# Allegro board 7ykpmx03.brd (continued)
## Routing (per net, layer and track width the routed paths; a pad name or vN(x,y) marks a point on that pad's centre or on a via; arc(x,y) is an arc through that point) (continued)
PE_CPU_OCP_15_DP: length 66.5
  TOP w0.127: 178.31,77.5 178.18,77.37 174.7,77.37 174.59,77.48 174.36,77.48 174.24,77.37 174.02,77.37 173.89,77.49 173.68,77.49 173.56,77.37 173.27,77.37 172.47,78.17 172.47,78.36 172.57,78.46 172.57,78.64 172.47,78.74 172.47,78.97 172.59,79.1 172.59,79.3 172.47,79.43 172.47,79.63 172.59,79.76 172.59,79.93 172.47,80.06 172.47,80.45 172.59,81.18 172.25,83.13 172.69,85.63 172.47,86.91 172.47,87.38 171.7,88.14 171.45,88.14 171.27,88.17 169.83,87.92 167.33,88.36 164.83,87.92 162.33,88.36 159.83,87.92 157.33,88.36 154.82,87.92 152.32,88.36 149.82,87.92 148.57,88.14 147.96,88.14 143.94,84.12 143.73,84.12 143.49,84.08 142.01,84.35 139.51,83.9 137.01,84.35 134.94,83.98 134.12,84.12 132.59,84.12 131.83,84.88 131.83,85.51 131.98,85.65 P_OCP.B66
  TOP w0.152: P_CPU_OCP_15_P.1 178.31,77.5
PE_OCP_CPU_0_DN: length 66.7
  TOP w0.127: P_OCP.A17 94.86,91.84 95.01,91.98 95.01,93.79 94.01,94.79 91.67,94.79 89.31,97.16 87.81,97.16 86.97,96.32 86.04,96.32 85.46,96.9 85.46,97.79 85.33,97.92 84.56,97.92 84.44,97.79 84.44,96.79 83.96,96.32 83.29,96.32 82.81,96.79 82.81,97.69 82.51,97.99 82.09,97.99 81.79,97.69 81.79,96.79 81.31,96.32 80.64,96.32 80.16,96.79 80.16,97.69 79.86,97.99 79.44,97.99 79.14,97.69 79.14,96.79 78.67,96.32 77.99,96.32 77.52,96.79 77.52,97.69 77.22,97.99 76.8,97.99 76.5,97.69 76.5,96.79 76.17,96.47 75.19,96.47 74.87,96.79 74.87,97.69 74.7,97.87 73.74,97.87 73.02,97.16 72.72,97.16 72.54,96.98 72.36,96.98 72.19,97.16 71.93,97.16 71.76,96.98 71.58,96.98 71.4,97.16 70.74,97.16 70.54,97.36 70.36,97.36 70.23,97.49 70.23,97.66 70.1,97.79 69.9,97.79 69.75,97.94 69.75,98.15 64.8,103.1 63.69,103.1 62.51,103.3 60.04,102.87 57.54,103.31 55.04,102.87 53.76,103.1 52.7,103.1 52.58,102.97
  TOP w0.152: P_OCP_CPU_0_N1.1 52.58,102.97
PE_OCP_CPU_0_DP: length 66.7
  TOP w0.127: P_OCP.A18 95.46,91.84 95.31,91.98 95.31,93.92 94.13,95.1 91.79,95.1 89.43,97.46 87.68,97.46 86.84,96.62 86.17,96.62 85.76,97.03 85.76,97.92 85.46,98.22 84.44,98.22 84.13,97.92 84.13,96.92 83.83,96.62 83.41,96.62 83.11,96.92 83.11,97.82 82.64,98.3 81.96,98.3 81.49,97.82 81.49,96.92 81.19,96.62 80.77,96.62 80.47,96.92 80.47,97.82 79.99,98.3 79.32,98.3 78.84,97.82 78.84,96.92 78.54,96.62 78.12,96.62 77.82,96.92 77.82,97.82 77.34,98.3 76.67,98.3 76.19,97.82 76.19,96.92 76.05,96.77 75.32,96.77 75.17,96.92 75.17,97.82 74.82,98.17 73.61,98.17 72.9,97.46 70.87,97.46 64.92,103.4 63.72,103.4 62.5,103.61 60.04,103.18 57.54,103.62 55.04,103.18 53.79,103.4 52.7,103.4 52.58,103.53
  TOP w0.152: P_OCP_CPU_0_P1.1 52.58,103.53
PE_OCP_CPU_1_DN: length 66.7
  TOP w0.127: 69.44,108.97 69.57,108.84 69.57,108.02 69.47,107.46 69.79,105.68 69.57,104.45 69.57,103.61 71.83,101.35 73.3,101.35 73.78,101.82 73.78,102.9 74.07,103.2 74.5,103.2 74.79,102.9 74.79,99.97 75.27,99.49 75.95,99.49 76.42,99.97 76.42,102.9 76.72,103.2 77.14,103.2 77.44,102.9 77.44,99.97 77.82,99.59 78.69,99.59 79.07,99.97 79.07,102.95 79.38,103.26 79.8,103.26 80.09,102.98 80.09,99.97 80.56,99.49 81.24,99.49 81.72,99.97 81.72,102.62 81.84,102.74 82.61,102.74 82.73,102.62 82.73,102.53 83.92,101.35 84.56,101.35 85.83,101.12 87.7,101.45 87.92,101.41 93.14,96.19 95.02,96.19 96.81,94.4 96.81,91.98 96.66,91.84 P_OCP.A20
  TOP w0.152: P_OCP_CPU_1_N1.1 69.44,108.97
PE_OCP_CPU_1_DP: length 66.7
  TOP w0.127: P_OCP.A21 97.26,91.84 97.11,91.98 97.11,94.53 95.15,96.49 93.27,96.49 88.07,101.69 87.7,101.76 85.83,101.43 84.58,101.65 84.05,101.65 83.04,102.66 83.04,102.74 82.73,103.05 81.72,103.05 81.41,102.74 81.41,100.09 81.11,99.8 80.69,99.8 80.39,100.09 80.39,103.1 79.93,103.57 79.25,103.57 78.76,103.08 78.76,100.09 78.57,99.9 77.94,99.9 77.75,100.09 77.75,103.03 77.27,103.5 76.59,103.5 76.12,103.03 76.12,100.09 75.82,99.8 75.4,99.8 75.1,100.09 75.1,103.03 74.62,103.5 73.95,103.5 73.47,103.03 73.47,101.95 73.17,101.65 71.96,101.65 69.88,103.73 69.88,104.42 70.1,105.68 69.78,107.46 69.88,108 69.88,108.84 70,108.97
  TOP w0.152: P_OCP_CPU_1_P1.1 70,108.97
PE_OCP_CPU_2_DN: length 66.6
  TOP w0.127: P_OCP.A23 98.46,91.84 98.61,91.98 98.61,94.76 94.88,98.49 93.51,98.49 86.86,105.14 86.41,105.14 85.44,104.17 85.01,104.17 84.29,104.89 84.29,105.32 85.15,106.18 85.15,106.36 84.61,106.9 84.43,106.9 84.01,106.49 83.58,106.49 82.86,107.21 82.86,107.64 83.54,108.31 83.54,108.49 82.99,109.03 82.81,109.03 82.37,108.59 81.94,108.59 81.22,109.31 81.22,109.74 81.52,110.03 81.52,110.51 77.65,114.38 76.15,114.38 76.02,114.25 75.82,114.25 75.69,114.38 75.49,114.38 75.36,114.25 75.13,114.25 75.01,114.38 74.78,114.38 74.68,114.27 74.47,114.27 74.37,114.38 74.17,114.38 74.04,114.25 73.84,114.25 73.71,114.38 73.33,114.38 69.55,118.16 69.55,118.95 69.66,119.59 69.32,121.51 69.55,122.79 69.55,122.94 67.08,125.4 66.94,125.4 66.82,125.53 66.82,125.67 66.52,125.96 64.14,125.96 64.01,125.83
  TOP w0.152: P_OCP_CPU_2_N1.1 64.01,125.83
PE_OCP_CPU_2_DP: length 66.6
  TOP w0.127: P_OCP.A24 99.06,91.84 98.91,91.98 98.91,94.89 95.01,98.79 93.64,98.79 86.99,105.45 86.29,105.45 85.32,104.48 85.14,104.48 84.6,105.02 84.6,105.2 85.46,106.06 85.46,106.49 84.74,107.21 84.31,107.21 83.89,106.79 83.71,106.79 83.17,107.33 83.17,107.51 83.84,108.18 83.84,108.62 83.12,109.33 82.69,109.33 82.25,108.89 82.07,108.89 81.53,109.43 81.53,109.61 81.82,109.91 81.82,110.63 77.77,114.68 73.46,114.68 69.85,118.29 69.85,118.92 69.97,119.59 69.63,121.51 69.85,122.76 69.85,123.06 66.65,126.26 64.14,126.26 64.01,126.39
  TOP w0.152: P_OCP_CPU_2_P1.1 64.01,126.39
PE_OCP_CPU_3_DN: length 66.5
  TOP w0.127: P_OCP.A26 100.26,91.84 100.41,91.98 100.41,92.71 100.62,93.92 100.41,95.12 100.41,95.48 94.97,100.91 93.65,100.91 86.95,107.62 86.95,108.29 88.43,109.77 88.43,109.95 87.89,110.49 87.71,110.49 86.02,108.8 85.59,108.8 84.87,109.52 84.87,109.95 87.82,112.9 87.82,113.32 87.52,113.62 87.1,113.62 84.15,110.67 83.71,110.67 83,111.39 83,111.82 86.07,114.9 86.07,115.32 85.77,115.62 85.35,115.62 82.48,112.75 81.81,112.75 81,113.56 81,114.41 81.22,115.64 80.8,118.04 81,119.21 81,120.27 80.87,120.4
  TOP w0.152: P_OCP_CPU_3_N1.1 80.87,120.4
PE_OCP_CPU_3_DP: length 66.5
  TOP w0.127: 81.43,120.4 81.31,120.27 81.31,119.19 81.11,118.04 81.53,115.64 81.31,114.39 81.31,113.69 81.94,113.06 82.36,113.06 85.22,115.92 85.9,115.92 86.38,115.45 86.38,114.77 83.3,111.7 83.3,111.52 83.84,110.98 84.02,110.98 86.97,113.93 87.64,113.93 88.12,113.45 88.12,112.78 85.17,109.83 85.17,109.65 85.71,109.11 85.89,109.11 87.58,110.79 88.01,110.79 88.73,110.07 88.73,109.64 87.25,108.16 87.25,107.74 93.78,101.22 95.1,101.22 100.71,95.6 100.71,95.15 100.93,93.92 100.71,92.69 100.71,91.98 100.86,91.84 P_OCP.A27
  TOP w0.152: P_OCP_CPU_3_P1.1 81.43,120.4
PE_OCP_CPU_4_DN: length 66.5
  TOP w0.127: 80.87,131.83 81,131.7 81,128.75 82.88,126.87 87.39,126.87 88.42,125.84 88.42,125.6 88.73,125.3 89.75,125.3 90.05,125.6 90.05,127.1 90.18,127.23 91.21,127.23 91.39,127.05 91.39,126.62 91.44,126.32 91.17,124.77 91.61,122.27 91.17,119.76 91.61,117.26 91.17,114.76 91.61,112.26 91.17,109.76 91.61,107.26 91.39,106.01 91.39,105.46 94.16,102.69 97.05,102.69 106.22,93.52 106.22,91.98 106.07,91.84 P_OCP.A30
  TOP w0.152: P_OCP_CPU_4_N.1 80.87,131.83
PE_OCP_CPU_4_DP: length 66.5
  TOP w0.127: P_OCP.A31 106.67,91.84 106.52,91.98 106.52,93.65 97.18,103 94.28,103 91.69,105.59 91.69,105.98 91.92,107.26 91.48,109.76 91.92,112.26 91.48,114.76 91.92,117.26 91.48,119.76 91.92,122.27 91.48,124.77 91.75,126.32 91.69,126.65 91.69,127.18 91.34,127.53 90.05,127.53 89.75,127.23 89.75,125.73 89.62,125.6 88.85,125.6 88.73,125.73 88.73,125.97 87.51,127.18 83.01,127.18 81.31,128.88 81.31,131.7 81.43,131.83
  TOP w0.152: P_OCP_CPU_4_P4.1 81.43,131.83
PE_OCP_CPU_5_DN: length 66.5
  TOP w0.127: P_OCP.A33 107.87,91.84 108.02,91.98 108.02,94.16 98.02,104.17 94.62,104.17 93.55,105.23 93.55,106.02 93.77,107.27 93.33,109.77 93.77,112.28 93.33,114.78 93.77,117.28 93.33,119.78 93.77,122.28 93.33,124.78 93.58,126.2 93.55,126.36 93.55,126.95 94.36,127.76 95.34,127.76 95.64,127.46 95.64,126.37 95.81,126.2 96.79,126.2 96.92,126.33 96.92,126.87 97.22,127.18 98.81,127.18 99.44,126.54 100.08,126.54 100.71,127.18 101.98,127.18 103.86,129.06 103.86,131.7 103.73,131.83
  TOP w0.152: P_OCP_CPU_5_N.1 103.73,131.83
PE_OCP_CPU_5_DP: length 66.5
  TOP w0.127: 104.29,131.83 104.17,131.7 104.17,128.93 102.11,126.87 100.84,126.87 100.2,126.24 99.31,126.24 98.68,126.87 97.35,126.87 97.22,126.75 97.22,126.2 96.92,125.9 95.69,125.9 95.34,126.25 95.34,127.33 95.21,127.46 94.49,127.46 93.85,126.82 93.85,126.39 93.89,126.2 93.64,124.78 94.08,122.28 93.64,119.78 94.08,117.28 93.64,114.78 94.08,112.28 93.64,109.77 94.08,107.27 93.85,106 93.85,105.36 94.74,104.47 98.14,104.47 108.32,94.29 108.32,91.98 108.47,91.84 P_OCP.A34
  TOP w0.152: P_OCP_CPU_5_P.1 104.29,131.83
PE_OCP_CPU_6_DN: length 66.6
  TOP w0.127: P_OCP.A36 109.67,91.84 109.82,91.98 109.82,95.25 110.13,95.55 110.54,95.55 111.02,96.04 111.02,96.47 110.89,96.6 110.06,96.6 108.3,96.9 107.9,96.9 107.59,97.21 107.59,98.17 108.02,98.6 108.27,98.6 108.37,98.62 110.45,98.25 112.43,98.6 112.81,98.6 112.94,98.73 112.94,99.57 112.81,99.69 112.44,99.69 110.88,99.42 109.16,99.72 108.99,99.69 108.4,99.69 107.97,100.13 107.97,101.09 108.27,101.4 109.35,101.4 110.48,101.2 111.61,101.4 111.89,101.4 112.05,101.56 112.05,102.11 112.23,103.16 112.05,104.22 112.05,104.47 111.92,104.6 110.36,104.6 110.13,104.37 110.13,102.79 109.83,102.49 108.59,102.49 108.28,102.79 108.28,104.47 108.15,104.6 107.01,104.6 106.73,104.32 106.73,103.9 106.51,102.65 106.73,101.39 106.73,100.37 106.43,100.06 105.03,100.06 104.55,100.54 104.55,102.84 104.38,103.01 104.13,103.01 103.11,102.83 102.08,103.01 101.64,103.01 101.34,103.32 101.34,104.37 101.64,104.67 101.98,104.67 103.03,104.49 104.09,104.67 104.43,104.67 104.55,104.8 104.55,105.89 103.86,106.58 103.86,108.84 103.73,108.97
  TOP w0.152: P_OCP_CPU_6_N.1 103.73,108.97
PE_OCP_CPU_6_DP: length 66.6
  TOP w0.127: 104.29,108.97 104.17,108.84 104.17,106.7 104.86,106.01 104.86,104.67 104.55,104.37 104.11,104.37 103.03,104.18 101.95,104.37 101.77,104.37 101.64,104.24 101.64,103.44 101.77,103.32 102.11,103.32 103.11,103.14 104.1,103.32 104.5,103.32 104.86,102.97 104.86,100.67 105.16,100.37 106.3,100.37 106.43,100.49 106.43,101.37 106.2,102.65 106.43,103.92 106.43,104.44 106.88,104.9 108.28,104.9 108.58,104.6 108.58,102.92 108.71,102.79 109.7,102.79 109.83,102.92 109.83,104.49 110.24,104.9 112.05,104.9 112.36,104.6 112.36,104.24 112.54,103.16 112.36,102.08 112.36,101.43 112.01,101.09 111.63,101.09 110.48,100.89 109.32,101.09 108.4,101.09 108.27,100.97 108.27,100.25 108.53,100 108.97,100 109.16,100.03 110.88,99.73 112.41,100 112.94,100 113.24,99.69 113.24,98.6 112.94,98.3 112.45,98.3 110.45,97.94 108.37,98.31 108.3,98.3 108.15,98.3 107.89,98.04 107.89,97.34 108.03,97.21 108.33,97.21 110.09,96.9 111.02,96.9 111.32,96.6 111.32,95.91 110.66,95.25 110.25,95.25 110.12,95.12 110.12,91.98 110.27,91.84 P_OCP.A37
  TOP w0.152: P_OCP_CPU_6_P.1 104.29,108.97
PE_OCP_CPU_7_DN: length 66.6
  TOP w0.127: 103.73,120.4 103.86,120.27 103.86,118.75 104.04,117.72 103.64,115.41 103.86,114.14 103.86,113.59 104.29,113.16 105.11,113.16 105.54,113.59 105.54,115.9 105.79,116.15 106.56,116.15 106.69,116.03 106.69,112.88 106.99,112.57 108.26,112.57 108.57,112.88 108.57,115.93 108.79,116.15 109.47,116.15 109.73,115.9 109.73,113.23 110.24,112.73 111.38,112.73 111.68,113.03 111.68,115.87 111.89,116.08 113.78,116.08 114.04,115.82 114.04,114.86 113.91,114.73 113.08,114.73 112.78,114.43 112.78,113.2 113.12,112.85 114.12,112.85 114.5,112.47 114.5,110.54 114.2,108.82 114.65,106.24 114.1,103.08 114.63,100.02 114.63,97.92 111.62,94.91 111.62,91.98 111.47,91.84 P_OCP.A39
  TOP w0.152: P_OCP_CPU_7_N.1 103.73,120.4
PE_OCP_CPU_7_DP: length 66.6
  TOP w0.127: P_OCP.A40 112.07,91.84 111.92,91.98 111.92,94.78 114.94,97.79 114.94,100.05 114.41,103.08 114.96,106.24 114.51,108.82 114.81,110.52 114.81,112.6 114.25,113.16 113.25,113.16 113.08,113.32 113.08,114.3 113.21,114.43 114.04,114.43 114.34,114.73 114.34,115.95 113.91,116.38 111.76,116.38 111.38,116 111.38,113.16 111.25,113.03 110.36,113.03 110.03,113.36 110.03,116.03 109.6,116.46 108.66,116.46 108.26,116.06 108.26,113 108.14,112.88 107.12,112.88 106.99,113 106.99,116.15 106.68,116.46 105.67,116.46 105.23,116.03 105.23,113.72 104.98,113.46 104.42,113.46 104.17,113.72 104.17,114.16 103.94,115.41 104.35,117.72 104.17,118.77 104.17,120.27 104.29,120.4
  TOP w0.152: P_OCP_CPU_7_P.1 104.29,120.4
PE_OCP_CPU_8_DN: length 66.5
  TOP w0.127: P_OCP.A44 118.78,91.84 118.93,91.98 118.93,92.33 118.49,92.77 118.49,93.19 118.32,94.16 118.49,95.13 118.49,95.91 116.1,98.3 116.1,100.37 116.15,100.62 115.72,103.08 116.29,106.35 115.85,108.86 116.14,110.49 116.03,111.12 116.03,112.6 116.64,113.21 117.71,113.21 117.95,113.45 117.95,114.21 117.73,114.43 116.54,114.43 116.22,114.75 116.22,116.08 116.53,116.38 119.25,116.38 119.68,115.95 119.68,113.54 119.81,113.41 121.03,113.41 121.16,113.54 121.16,116 121.49,116.33 122.55,116.33 122.86,116.03 122.86,114.02 123.22,113.66 123.83,113.66 123.95,113.79 123.95,116 124.26,116.31 125.35,116.31 125.65,116 125.65,112.78 125.78,112.65 126.59,112.65 126.72,112.78 126.72,113.29 127.02,114.96 126.57,117.46 126.78,118.64 126.72,119 126.72,120.27 126.59,120.4
  TOP w0.152: P_OCP_CPU_8_N.1 126.59,120.4
PE_OCP_CPU_8_DP: length 66.5
  TOP w0.127: P_OCP.A45 119.38,91.84 119.23,91.98 119.23,92.46 118.8,92.89 118.8,93.22 118.63,94.16 118.8,95.11 118.8,96.04 116.41,98.42 116.41,100.34 116.46,100.62 116.03,103.08 116.6,106.35 116.16,108.86 116.45,110.49 116.33,111.15 116.33,112.47 116.76,112.9 117.83,112.9 118.25,113.32 118.25,114.34 117.86,114.73 116.66,114.73 116.53,114.87 116.53,115.95 116.65,116.08 119.13,116.08 119.38,115.82 119.38,113.41 119.69,113.11 121.16,113.11 121.46,113.41 121.46,115.87 121.62,116.03 122.43,116.03 122.55,115.9 122.55,113.9 123.09,113.36 123.95,113.36 124.26,113.67 124.26,115.87 124.38,116 125.22,116 125.35,115.87 125.35,112.65 125.65,112.34 126.72,112.34 127.03,112.65 127.03,113.26 127.33,114.96 126.88,117.46 127.09,118.64 127.03,119.02 127.03,120.27 127.15,120.4
  TOP w0.152: P_OCP_CPU_8_P.1 127.15,120.4
PE_OCP_CPU_9_DN: length 66.5
  TOP w0.127: P_OCP.A47 120.58,91.84 120.73,91.98 120.73,92.71 120.5,93.98 120.73,95.26 120.73,95.43 120.6,95.55 120.44,95.55 119.99,96.01 119.99,96.9 120.29,97.21 122.39,97.21 122.72,97.53 122.72,98.09 122.5,98.3 122,98.3 121.61,98.23 120.25,98.47 119.27,98.3 118.44,98.3 118.06,98.68 118.06,99.55 118.44,99.93 118.88,99.93 120.18,100.16 121.35,99.95 121.68,99.95 121.8,100.08 121.8,100.82 121.61,101.02 120.34,101.24 118.67,100.95 118.44,100.95 118.13,101.25 118.13,101.75 117.94,102.88 118.13,104.02 118.13,104.65 118.44,104.95 119.78,104.95 120.08,104.65 120.08,103 120.21,102.87 120.97,102.87 121.1,103 121.1,104.65 121.41,104.95 123.06,104.95 123.51,104.51 123.51,102.89 123.73,101.63 123.51,100.38 123.55,100.19 123.55,99.57 123.9,99.21 124.33,99.21 124.88,99.76 124.88,101.38 125.18,101.69 126.82,101.69 126.95,101.82 126.95,102.85 126.82,102.97 125.02,102.97 124.71,103.28 124.71,104.27 125.04,104.6 125.27,104.6 126.37,104.79 127.46,104.6 127.92,104.6 128.05,104.73 128.05,105.52 127.92,105.65 127.03,105.65 126.72,105.96 126.72,108.84 126.59,108.97
  TOP w0.152: P_OCP_CPU_9_N.1 126.59,108.97
PE_OCP_CPU_9_DP: length 66.5
  TOP w0.127: P_OCP.A48 121.18,91.84 121.03,91.98 121.03,92.73 120.81,93.98 121.03,95.24 121.03,95.55 120.73,95.86 120.57,95.86 120.29,96.14 120.29,96.77 120.42,96.9 122.51,96.9 123.02,97.41 123.02,98.21 122.63,98.6 121.97,98.6 121.61,98.54 120.25,98.78 119.24,98.6 118.56,98.6 118.36,98.8 118.36,99.42 118.56,99.62 118.91,99.62 120.18,99.85 121.32,99.64 121.8,99.64 122.11,99.95 122.11,100.95 121.75,101.3 120.34,101.54 118.65,101.25 118.56,101.25 118.44,101.38 118.44,101.78 118.24,102.88 118.44,103.99 118.44,104.52 118.56,104.65 119.65,104.65 119.78,104.52 119.78,102.87 120.08,102.57 121.1,102.57 121.41,102.87 121.41,104.52 121.53,104.65 122.94,104.65 123.2,104.38 123.2,102.87 123.42,101.63 123.2,100.39 123.24,100.16 123.24,99.44 123.77,98.91 124.46,98.91 125.18,99.63 125.18,101.26 125.31,101.38 126.95,101.38 127.25,101.69 127.25,102.97 126.95,103.28 125.15,103.28 125.02,103.41 125.02,104.15 125.17,104.3 125.3,104.3 126.37,104.48 127.43,104.3 128.05,104.3 128.35,104.6 128.35,105.65 128.05,105.96 127.15,105.96 127.03,106.08 127.03,108.84 127.15,108.97
  TOP w0.152: P_OCP_CPU_9_P.1 127.15,108.97
PE_OCP_CPU_10_DN: length 66.6
  TOP w0.127: P_OCP.A50 122.38,91.84 122.53,91.98 122.53,92.73 122.35,93.79 122.53,94.85 122.53,95.22 130.68,103.38 135.13,103.38 137.16,105.41 137.16,105.97 137.38,107.23 136.94,109.73 137.38,112.23 136.94,114.73 137.38,117.23 136.94,119.73 137.38,122.23 136.95,124.67 137.16,125.86 137.16,126.11 136.45,126.82 135.64,126.82 135.28,126.47 135.28,125.5 134.75,124.97 133.29,124.97 132.75,125.5 132.75,126.53 132.46,126.82 128.65,126.82 126.85,128.63 126.85,131.44 126.72,131.57
  TOP w0.152: P_OCP_CPU_10_N.1 126.72,131.57
PE_OCP_CPU_10_DP: length 66.6
  TOP w0.127: 127.28,131.57 127.15,131.44 127.15,128.75 128.78,127.13 132.59,127.13 133.06,126.66 133.06,125.63 133.41,125.27 134.62,125.27 134.98,125.63 134.98,126.59 135.51,127.13 136.58,127.13 137.46,126.24 137.46,125.83 137.26,124.67 137.69,122.23 137.25,119.73 137.69,117.23 137.25,114.73 137.69,112.23 137.25,109.73 137.69,107.23 137.46,105.95 137.46,105.28 135.25,103.07 130.81,103.07 122.83,95.1 122.83,94.82 122.66,93.79 122.83,92.76 122.83,91.98 122.98,91.84 P_OCP.A51
  TOP w0.152: P_OCP_CPU_10_P.1 127.28,131.57
PE_OCP_CPU_11_DN: length 66.6
  TOP w0.127: 149.45,131.83 149.58,131.7 149.58,128.8 147.91,127.13 143.64,127.13 142.91,126.4 142.91,125.82 142.62,125.53 141.6,125.53 141.38,125.75 141.38,126.72 140.97,127.13 139.9,127.13 139.14,126.36 139.14,125.95 138.92,124.7 139.36,122.2 138.92,119.7 139.36,117.2 138.92,114.7 139.36,112.2 138.92,109.7 139.36,107.19 139.14,105.94 139.14,104.77 136.14,101.78 131.7,101.78 124.33,94.41 124.33,91.98 124.18,91.84 P_OCP.A53
  TOP w0.152: P_OCP_CPU_11_N.1 149.45,131.83
PE_OCP_CPU_11_DP: length 66.6
  TOP w0.127: P_OCP.A54 124.78,91.84 124.63,91.98 124.63,94.28 131.83,101.47 136.27,101.47 139.45,104.65 139.45,105.92 139.67,107.19 139.23,109.7 139.67,112.2 139.23,114.7 139.67,117.2 139.23,119.7 139.67,122.2 139.23,124.7 139.45,125.93 139.45,126.24 140.03,126.82 140.84,126.82 141.07,126.59 141.07,125.63 141.48,125.22 142.75,125.22 143.22,125.69 143.22,126.28 143.76,126.82 148.04,126.82 149.89,128.67 149.89,131.7 150.01,131.83
  TOP w0.152: P_OCP_CPU_11_P.1 150.01,131.83
PE_OCP_CPU_12_DN: length 66.6
  TOP w0.127: P_OCP.A56 125.98,91.84 126.13,91.98 126.13,93.54 132.74,100.15 137.31,100.15 142.8,105.64 143.69,105.64 144.4,104.93 144.58,104.93 145.12,105.47 145.12,105.65 142.94,107.83 142.94,108.27 143.66,108.98 144.09,108.98 146.27,106.8 146.45,106.8 146.99,107.34 146.99,107.52 144.81,109.71 144.81,110.14 145.53,110.86 145.96,110.86 148.14,108.67 148.32,108.67 148.86,109.21 148.86,109.39 146.68,111.58 146.68,112.06 147.35,112.73 147.83,112.73 148.77,111.79 148.95,111.79 149.58,112.42 149.58,113.05 149.8,114.3 149.36,116.8 149.7,118.72 149.58,119.39 149.58,120.27 149.45,120.4
  TOP w0.152: P_OCP_CPU_12_N.1 149.45,120.4
PE_OCP_CPU_12_DP: length 66.6
  TOP w0.127: P_OCP.A57 126.58,91.84 126.43,91.98 126.43,93.41 132.87,99.85 137.44,99.85 142.93,105.34 143.56,105.34 144.27,104.62 144.71,104.62 145.43,105.34 145.43,105.78 143.24,107.96 143.24,108.14 143.78,108.68 143.96,108.68 146.15,106.5 146.58,106.5 147.3,107.22 147.3,107.65 145.11,109.83 145.11,110.01 145.65,110.55 145.83,110.55 148.02,108.37 148.45,108.37 149.17,109.09 149.17,109.52 146.98,111.7 146.98,111.93 147.48,112.42 147.7,112.42 148.64,111.48 149.08,111.48 149.89,112.29 149.89,113.02 150.11,114.3 149.67,116.8 150.01,118.72 149.89,119.41 149.89,120.27 150.01,120.4
  TOP w0.152: P_OCP_CPU_12_P.1 150.01,120.4
PE_OCP_CPU_13_DN: length 66.6
  TOP w0.127: 160.88,108.97 161.01,108.84 161.01,105.58 158.81,103.38 156.27,103.38 155.76,102.87 155.34,102.87 155.04,103.17 155.04,103.41 154.56,103.89 153.62,103.89 153.11,103.38 151.97,103.38 146.94,98.35 146.05,98.35 145.75,98.65 145.75,102.56 145.27,103.04 144.6,103.04 144.12,102.56 144.12,98.42 143.99,98.3 143.23,98.3 143.1,98.42 143.1,102.05 142.63,102.53 141.95,102.53 141.47,102.05 141.47,98.48 141.35,98.35 141.07,98.35 139.9,98.55 137.48,98.13 134.98,98.57 133.73,98.35 133.22,98.35 127.93,93.06 127.93,91.98 127.78,91.84 P_OCP.A59
  TOP w0.152: P_OCP_CPU_13_N.1 160.88,108.97
PE_OCP_CPU_13_DP: length 66.6
  TOP w0.127: 161.44,108.97 161.32,108.84 161.32,105.45 158.93,103.07 156.39,103.07 155.89,102.57 155.21,102.57 154.74,103.04 154.74,103.28 154.44,103.58 153.75,103.58 153.24,103.07 152.1,103.07 147.07,98.04 145.92,98.04 145.44,98.52 145.44,102.43 145.15,102.73 144.72,102.73 144.43,102.43 144.43,98.3 144.12,97.99 143.1,97.99 142.8,98.3 142.8,101.92 142.5,102.22 142.08,102.22 141.78,101.92 141.78,98.35 141.47,98.04 141.04,98.04 139.9,98.24 137.48,97.82 134.98,98.26 133.76,98.04 133.35,98.04 128.23,92.93 128.23,91.98 128.38,91.84 P_OCP.A60
  TOP w0.152: P_OCP_CPU_13_P.1 161.44,108.97
PE_OCP_CPU_14_DN: length 66.7
  TOP w0.127: P_OCP.A62 129.58,91.84 129.73,91.98 129.73,92.72 133.32,96.32 134.03,96.32 135.8,96.63 138.3,96.19 140.31,96.54 142.81,96.1 144.28,96.36 144.52,96.32 145.24,96.32 146.25,95.3 146.86,95.3 149.4,97.84 150.37,97.84 151.18,97.03 151.18,95.62 148.44,92.88 148.44,92.7 149.53,91.62 149.71,91.62 151.34,93.26 152.04,93.26 152.52,92.78 152.52,91.69 152.64,91.57 153.41,91.57 153.54,91.69 153.54,92.91 154.01,93.38 154.69,93.38 155.16,92.91 155.16,91.69 155.29,91.57 156.06,91.57 156.18,91.69 156.18,92.78 156.66,93.26 157.33,93.26 157.83,92.76 157.83,91.69 157.96,91.57 158.7,91.57 158.93,91.8 158.93,92.53 159.23,92.84 160.32,92.84 160.63,92.53 160.63,91.69 160.76,91.57 161.34,91.57 161.72,91.95 161.72,92.41 161.01,96.47 161.01,97.41 160.88,97.54
  TOP w0.152: P_OCP_CPU_14_N.1 160.88,97.54
PE_OCP_CPU_14_DP: length 66.7
  TOP w0.127: P_OCP.A63 130.18,91.84 130.03,91.98 130.03,92.6 133.45,96.01 134.06,96.01 135.8,96.32 138.3,95.88 140.31,96.23 142.81,95.79 144.28,96.05 144.49,96.01 145.11,96.01 146.13,95 146.99,95 149.53,97.54 150.24,97.54 150.88,96.9 150.88,95.74 148.14,93.01 148.14,92.58 149.4,91.32 149.83,91.32 151.47,92.95 151.91,92.95 152.21,92.65 152.21,91.57 152.52,91.26 153.54,91.26 153.84,91.57 153.84,92.78 154.14,93.08 154.56,93.08 154.86,92.78 154.86,91.57 155.17,91.26 156.18,91.26 156.49,91.57 156.49,92.65 156.79,92.95 157.21,92.95 157.53,92.63 157.53,91.57 157.83,91.26 158.83,91.26 159.23,91.67 159.23,92.41 159.36,92.53 160.2,92.53 160.32,92.41 160.32,91.57 160.63,91.26 161.47,91.26 162.03,91.82 162.03,92.44 161.32,96.49 161.32,97.41 161.44,97.54
  TOP w0.152: P_OCP_CPU_14_P.1 161.44,97.54
PE_OCP_CPU_15_DN: length 66.6
  TOP w0.127: 178.31,103.53 178.18,103.4 176.53,103.4 173.05,99.92 172.41,96.26 172.72,94.46 172.54,93.43 172.54,92.99 169.6,90.04 169.34,90.04 168.95,89.98 167.32,90.26 163.92,89.66 161.42,90.11 158.94,89.67 156.44,90.11 154.3,89.73 151.8,90.17 149.81,89.82 148.55,90.04 147.83,90.04 145.67,92.2 145.67,92.96 145.16,93.47 144.4,93.47 143.21,94.67 142.75,94.67 142.36,94.6 140.27,94.97 138.56,94.67 133.74,94.67 131.53,92.46 131.53,91.98 131.38,91.84 P_OCP.A65
  TOP w0.152: P_OCP_CPU_15_N.1 178.31,103.53
PE_OCP_CPU_15_DP: length 66.6
  TOP w0.127: 178.31,102.97 178.18,103.1 176.65,103.1 173.33,99.78 172.71,96.26 173.03,94.46 172.85,93.41 172.85,92.86 169.72,89.74 169.37,89.74 168.95,89.67 167.32,89.95 163.92,89.36 161.42,89.8 158.94,89.36 156.44,89.8 154.3,89.42 151.8,89.86 149.81,89.51 148.53,89.74 147.7,89.74 145.36,92.08 145.36,92.84 145.03,93.17 144.27,93.17 143.08,94.36 142.78,94.36 142.36,94.29 140.27,94.66 138.59,94.36 136.58,94.36 136.4,94.18 136.22,94.18 136.04,94.36 135.76,94.36 135.56,94.16 135.26,94.16 135.05,94.36 134.85,94.36 134.65,94.16 134.42,94.16 134.21,94.36 133.87,94.36 131.83,92.33 131.83,91.98 131.98,91.84 P_OCP.A66
  TOP w0.152: P_OCP_CPU_15_P.1 178.31,102.97
PERST0_N: length 54.7
  TOP w0.102: v1(46.35,80.01) 43.94,82.42 R15.2 ; v1(89.53,84.71) 90.66,85.84 P_OCP.B10
  BOTTOM w0.102: v1(89.53,84.71) 88.73,85.51 83.67,85.51 77.67,79.5 57.91,79.5 56.26,77.85 49.91,77.85 48.26,79.5 46.86,79.5 v1(46.35,80.01)
PERST1_N: length 61.3
  TOP w0.102: R16.1 42.41,81.4 v1(42.16,81.15) ; v1(90.93,92.46) 91.06,92.46 91.26,92.25 P_OCP.A11
  BOTTOM w0.102: v1(90.93,92.46) 90.93,91.64 91.36,91.21 91.36,89.64 90.42,88.7 90.42,87.63 88.62,85.83 83.62,85.83 78.44,80.64 59.56,80.64 56.9,83.31 49.91,83.31 47.24,80.64 42.67,80.64 v1(42.16,81.15)
PERST2_N: length 55.9
  TOP w0.102: R2.1 39.75,81.15 v1(39.24,80.64) ; v1(32,88.27) 32,88.65 33.15,89.79 61.85,89.79 64.77,92.71 70.59,92.71 72.25,91.05 P_OCP.OCP_A1
  BOTTOM w0.102: v1(39.24,80.64) 38.23,80.64 32,86.87 v1(32,88.27)
PERST3_N: length 59.5
  TOP w0.102: v1(31.12,88.27) 33.66,90.8 60.71,90.8 63.37,93.47 71.78,93.47 73.53,91.72 73.53,91.18 P_OCP.OCP_A2 ; R8.1 39.75,81.79 v1(39.24,81.28)
  BOTTOM w0.102: v1(39.24,81.28) 39.12,81.15 38.35,81.15 32.64,86.87 32.64,88.52 32.26,88.9 31.75,88.9 v1(31.12,88.27)
PRSNTB0_N: length 11.1
  TOP w0.102: P_OCP.B42 113.27,87.49 114.05,88.27 114.05,91.69 115.95,93.6 TP1.TEST 116.97,94.44 117.4,94.87 R1.1
PRSNTB1_N: length 7.8
  TOP w0.102: v1(113.92,94.23) 113.27,93.59 P_OCP.A42
  BOTTOM w0.102: v1(113.92,94.23) 113.33,94.82 R3.1 114.48,96.77 TP2.TEST
PRSNTB2_N: length 15.4
  TOP w0.102: P_OCP.A12 91.86,93.05 91.31,93.6 v1(90.8,93.6)
  BOTTOM w0.102: R4.1 89.71,83.36 90.55,84.2 TP13.TEST 90.55,86.74 91.31,87.5 91.31,88.49 92.33,89.51 92.33,91.08 92,91.41 92,92.66 91.06,93.6 v1(90.8,93.6)
PRSNTB3_N: length 12.9
  TOP w0.102: TP6.TEST 142.93,90.86 R10.1 142.93,87.93 141.44,86.45 P_OCP.B70
PWRBRK_N: length 15.3
  TOP w0.102: R17.2 144.09,89.56 144.4,89.25 R18.2 144.02,88.9 143.64,88.52 143.64,87.5 141.61,85.47 133.35,85.47 133.18,85.64 P_OCP.B68
RC19004_VDDCLK1: length 5
  TOP w0.102: U19.10 v1(65.01,219.73) 64.52,220.22 64.52,220.34 L7.2 C143.1
  BOTTOM w0.254: v1(65.01,219.73) 65.02,219.71 65.92,219.71
RC19004_VDDCLK2: length 4.6
  TOP w0.102: L8.2 65.65,215.56 C145.1 65.66,217.13 v1(65.95,217.43) 65.98,217.45 U19.15
  BOTTOM w0.254: C144.1 v1(65.95,217.43)
RC19004_VDDCLK3: length 4.1
  TOP w0.254: C149.1 67.89,215.95 67.82,216.03 v1(67.82,216.25) U19.18
  BOTTOM w0.254: C148.1 v1(67.82,216.25) L9.2
RC19004_VDDCLK4: length 4.7
  TOP w0.102: L10.2 C151.1 C150.1 70.74,219.33 U19.25
REFCLK0_DN: length 154.9
  TOP w0.127: v1(92.94,88.03) 93.21,87.76 93.21,87.29 93.06,87.14 P_OCP.B14 ; 64.8,204.65 64.67,204.52 64.67,202.78 64.89,201.51 64.61,199.89 64.67,199.54 64.67,199.19 64.77,198.59 64.67,197.99 64.67,197.76 v1(64.94,197.49) ; 64.8,204.65 64.67,204.77 64.67,205.49 64.8,205.61 v1(64.9,205.61) 65.15,205.87 R196.2 ; 64.8,204.65 R78.2 ; R111.2 v1(62.86,207.9)
  BOTTOM w0.127: v1(64.94,197.49) 64.67,197.76 64.67,198.02 64.36,198.32 63.48,198.32 62.69,197.54 62.69,193.12 63.75,192.05 63.75,141.3 68.4,136.65 68.4,107.57 71.5,104.47 87.12,104.47 96.77,94.82 96.77,91.24 94.97,89.43 93.7,89.43 93.21,88.94 93.21,88.3 v1(92.94,88.03) ; v1(64.9,205.61) 64.8,205.61 64.67,205.74 64.67,206.35 63.96,207.06 62.81,207.06 62.38,207.49 62.38,207.77 62.51,207.9 v1(62.86,207.9)
REFCLK0_DP: length 154.9
  TOP w0.127: P_OCP.B15 93.66,87.14 93.51,87.28 93.51,87.76 v1(93.79,88.03) ; R110.2 v1(61.59,207.9) ; 64.24,204.65 64.36,204.77 64.36,205.49 64.24,205.61 v1(64.14,205.61) 63.88,205.87 R195.2 ; 64.24,204.65 64.36,204.52 64.36,202.76 64.58,201.51 64.3,199.89 64.36,199.52 64.36,199.16 64.46,198.59 64.36,198.01 64.36,197.76 v1(64.09,197.49) ; 64.24,204.65 R72.2
  BOTTOM w0.127: v1(61.59,207.9) 61.95,207.9 62.08,207.77 62.08,207.37 62.69,206.76 63.83,206.76 64.36,206.22 64.36,205.74 64.24,205.61 v1(64.14,205.61) ; v1(93.79,88.03) 93.51,88.3 93.51,88.82 93.83,89.13 95.1,89.13 97.08,91.11 97.08,94.95 87.25,104.77 71.63,104.77 68.71,107.7 68.71,136.78 64.06,141.43 64.06,190.7 64.14,190.78 64.14,191.01 64.06,191.08 64.06,191.34 64.21,191.49 64.21,191.69 64.06,191.85 64.06,192.18 63.96,192.28 63.96,192.46 63.83,192.58 63.65,192.58 63.49,192.75 63.49,192.96 63.36,193.09 63.14,193.09 62.99,193.24 62.99,193.68 63.17,193.85 63.17,194.13 62.99,194.31 62.99,194.54 63.2,194.74 63.2,194.95 62.99,195.15 62.99,195.35 63.16,195.52 63.16,195.7 62.99,195.86 62.99,196.09 63.16,196.25 63.16,196.43 62.99,196.6 62.99,197.41 63.6,198.02 64.24,198.02 64.36,197.89 64.36,197.76 v1(64.09,197.49)
REFCLK0_R_DN: length 15.3
  TOP w0.127: U19.13 65.4,218.53 65.35,218.58 63.51,218.58 62.75,217.82 62.75,217.29 62.53,216.04 62.93,213.74 62.75,212.7 62.75,212.08 64.67,210.16 64.67,207.44 64.8,207.31 R196.1
REFCLK0_R_DP: length 15.8
  TOP w0.127: U19.12 65.4,218.93 65.35,218.88 63.38,218.88 62.44,217.94 62.44,217.32 62.22,216.04 62.62,213.74 62.44,212.73 62.44,211.95 64.36,210.03 64.36,207.44 64.24,207.31 R195.1
REFCLK1_DN: length 163.3
  TOP w0.127: R83.2 67.34,204.65 67.21,204.77 67.21,205.49 67.34,205.61 v1(67.44,205.61) 67.69,205.87 R198.2 ; R113.2 v1(62.86,203.33) ; v1(92.95,92.63) 93.22,92.36 93.22,91.89 93.23,91.89 93.23,91.71 93.06,91.54 P_OCP.A14
  BOTTOM w0.127: v1(92.95,92.63) 93.22,92.36 93.22,91.77 93.81,91.19 94.67,91.19 95.3,91.82 95.3,93.9 94.28,94.92 86.61,94.92 84.66,92.96 81.38,92.96 79.43,94.92 79.43,95.55 73.96,101.02 61.54,101.02 56.95,105.61 56.95,192.28 58.5,193.83 58.5,200.05 60.91,202.46 62.05,202.46 62.41,202.82 62.41,203.23 62.51,203.33 ; 62.51,203.33 62.41,203.43 62.41,203.68 62.92,204.19 66.5,204.19 67.18,204.88 67.18,205.36 v1(67.44,205.61) ; 62.51,203.33 v1(62.86,203.33)
REFCLK1_DP: length 163.3
  TOP w0.127: R197.2 66.42,205.87 v1(66.68,205.61) 66.78,205.61 66.9,205.49 66.9,204.77 66.78,204.65 R81.2 ; v1(93.8,92.63) 93.53,92.36 93.53,92.02 93.53,92.01 93.53,91.76 93.66,91.63 P_OCP.A15 ; R112.2 v1(61.59,203.33)
  BOTTOM w0.127: v1(61.59,203.33) 61.95,203.33 ; 61.95,203.33 62.1,203.17 62.1,202.94 61.93,202.77 60.78,202.77 60.53,202.51 60.34,202.51 60.21,202.39 60.21,202.2 60.02,202.01 59.75,202.01 59.63,201.88 59.63,201.61 59.42,201.41 59.19,201.41 59,201.22 59,200.99 58.74,200.72 58.53,200.72 58.39,200.58 58.39,200.38 58.19,200.18 58.19,199.85 58.06,199.72 58.06,199.47 58.19,199.34 58.19,193.95 56.64,192.41 56.64,105.49 61.42,100.71 73.84,100.71 79.12,95.43 79.12,94.79 81.26,92.66 84.79,92.66 86.74,94.61 91.57,94.61 91.74,94.44 92.02,94.44 92.2,94.61 92.46,94.61 92.61,94.46 92.94,94.46 93.09,94.61 93.34,94.61 93.47,94.49 93.78,94.49 93.9,94.61 94.16,94.61 95,93.78 95,91.95 94.54,91.49 93.93,91.49 93.53,91.9 93.53,92.36 v1(93.8,92.63) ; 61.95,203.33 62.1,203.48 62.1,203.81 62.79,204.5 66.37,204.5 66.88,205 66.88,205.41 v1(66.68,205.61)
REFCLK1_R_DN: length 11
  TOP w0.127: R198.1 67.34,207.31 67.21,207.44 67.21,207.93 67.1,208.57 67.43,210.49 67.21,211.77 67.21,212.45 66.93,212.73 66.93,213.44 66.74,214.52 66.93,215.6 66.93,216.09 67.37,216.54 67.37,216.86 67.42,216.91 U19.17
REFCLK1_R_DP: length 11
  TOP w0.127: R197.1 66.78,207.31 66.9,207.44 66.9,207.9 66.79,208.57 67.12,210.49 66.9,211.74 66.9,212.32 66.62,212.6 66.62,213.41 66.43,214.52 66.62,215.63 66.62,216.22 67.07,216.66 67.07,216.86 67.02,216.91 U19.16
REFCLK2_DN: length 169.9
  TOP w0.127: R79.2 69.88,204.65 ; 69.88,204.65 69.75,204.77 69.75,205.49 69.88,205.61 v1(69.98,205.61) 70.23,205.87 R200.2 ; 69.88,204.65 69.75,204.52 69.75,202.94 69.97,201.66 69.56,199.29 69.75,198.2 69.75,197.76 v1(70.02,197.49) ; P_OCP.OCP_B11 79.07,85.75 79.2,85.62 79.2,82.29 80.14,81.36 81.89,81.36 82.04,81.51 82.89,81.51 v1(83.25,81.15) ; 62.86,202.06 v1(62.86,201.42)
  BOTTOM w0.127: v1(62.86,201.42) 62.51,201.42 62.41,201.52 62.41,201.83 62.56,201.98 66.85,201.98 67.23,202.36 67.23,203.3 67.72,203.78 68.63,203.78 69.72,204.88 69.72,205.36 v1(69.98,205.61) ; v1(70.02,197.49) 69.75,197.21 69.75,144.88 80.01,134.62 80.01,119.13 98.86,100.28 98.86,89.71 95.3,86.16 95.3,84.96 91.69,81.36 83.47,81.36 v1(83.25,81.15)
REFCLK2_DP: length 169.9
  TOP w0.127: R199.2 68.96,205.87 v1(69.22,205.61) 69.32,205.61 69.44,205.49 69.44,204.77 69.32,204.65 ; R73.2 69.32,204.65 ; 69.32,204.65 69.44,204.52 69.44,202.91 69.66,201.66 69.25,199.29 69.44,198.17 69.44,197.76 v1(69.17,197.49) ; v1(83.25,82) 83.07,81.81 81.91,81.81 81.76,81.66 80.26,81.66 79.51,82.42 79.51,85.6 79.67,85.76 P_OCP.OCP_B12 ; 61.59,202.06 v1(61.59,201.42)
  BOTTOM w0.127: v1(83.25,82) 83.59,81.66 85.22,81.66 85.39,81.84 85.67,81.84 85.85,81.66 86.16,81.66 86.31,81.81 86.56,81.81 86.72,81.66 87.05,81.66 87.2,81.81 87.48,81.81 87.63,81.66 87.91,81.66 88.06,81.81 88.39,81.81 88.54,81.66 88.85,81.66 89,81.81 89.28,81.81 89.43,81.66 89.74,81.66 89.89,81.81 90.14,81.81 90.3,81.66 90.63,81.66 90.75,81.79 91.06,81.79 91.19,81.66 91.57,81.66 91.74,81.84 91.74,81.99 91.97,82.22 92.13,82.22 92.38,82.47 92.38,82.58 92.56,82.75 92.66,82.75 95,85.09 95,86.28 98.55,89.84 98.55,100.15 79.71,119 79.71,134.49 69.44,144.76 69.44,197.21 v1(69.17,197.49) ; v1(61.59,201.42) 61.95,201.42 62.1,201.57 62.1,201.96 62.43,202.29 66.73,202.29 66.93,202.49 66.93,203.43 67.59,204.09 68.5,204.09 69.42,205 69.42,205.41 v1(69.22,205.61)
REFCLK2_R_DN: length 11.2
  TOP w0.127: U19.20 68.62,216.91 68.57,216.86 68.57,216.67 69.75,215.49 69.75,214.83 69.97,213.55 69.53,211.05 69.92,208.85 69.75,207.87 69.75,207.44 69.88,207.31 R200.1
REFCLK2_R_DP: length 11.2
  TOP w0.127: R199.1 69.32,207.31 69.44,207.44 69.44,207.9 69.61,208.85 69.22,211.05 69.66,213.55 69.44,214.8 69.44,215.37 68.27,216.55 68.27,216.86 68.22,216.91 U19.19
REFCLK3_DN: length 152.8
  TOP w0.127: R117.2 v1(62.86,199.52) ; R70.2 72.77,205.8 v1(72.58,205.61) 72.48,205.61 72.35,205.49 72.35,204.77 72.48,204.65 R84.2 ; P_OCP.OCP_A11 79.07,91.84 79.21,91.98 79.21,92.85 80.01,93.65 81.15,93.65 81.48,93.98 81.48,94.97 v1(81.21,95.24)
  BOTTOM w0.127: v1(72.58,205.61) 72.34,205.37 72.34,204.93 71.2,203.78 70.05,203.78 69.52,203.25 69.52,201.32 68.48,200.28 62.66,200.28 62.41,200.03 62.41,199.62 62.51,199.52 ; v1(62.86,199.52) 62.51,199.52 ; 62.51,199.52 62.38,199.39 62.38,199.04 61.01,197.66 61.01,190.96 59.11,189.05 59.11,106.04 62.23,102.92 75.69,102.92 81.6,97.02 82.36,97.02 83.64,95.73 83.64,94.34 82.98,93.68 81.92,93.68 81.48,94.11 81.48,94.97 v1(81.21,95.24)
REFCLK3_DP: length 152.9
  TOP w0.127: P_OCP.OCP_A12 79.67,91.84 79.52,91.98 79.52,92.73 80.14,93.34 81.28,93.34 81.79,93.85 81.79,94.97 v1(82.06,95.24) ; R201.2 71.5,205.93 v1(71.82,205.61) 71.92,205.61 72.05,205.49 72.05,204.77 71.92,204.65 R82.2 ; R116.2 v1(61.59,199.52)
  BOTTOM w0.127: 61.95,199.52 62.1,199.67 62.1,200.15 62.53,200.58 68.35,200.58 69.22,201.45 69.22,203.38 69.93,204.09 71.07,204.09 72.03,205.05 72.03,205.4 v1(71.82,205.61) ; 61.95,199.52 v1(61.59,199.52) ; 61.95,199.52 62.08,199.39 62.08,199.16 60.71,197.79 60.71,197.46 60.43,197.18 60.43,196.88 60.71,196.6 60.71,196.16 60.43,195.89 60.43,195.71 60.71,195.43 60.71,195.02 60.45,194.77 60.45,194.54 60.71,194.28 60.71,193.8 60.41,193.51 60.41,193.33 60.71,193.04 60.71,192.61 60.58,192.48 60.58,191.77 60.71,191.64 60.71,191.08 58.8,189.18 58.8,105.92 62.1,102.62 75.56,102.62 81.47,96.71 82.23,96.71 83.34,95.61 83.34,94.46 82.85,93.98 82.04,93.98 81.79,94.23 81.79,94.97 v1(82.06,95.24)
REFCLK3_R_DN: length 13.7
  TOP w0.127: R70.1 72.42,207.31 72.29,207.44 72.29,207.87 72.07,209.12 72.36,210.77 72.29,211.18 72.29,211.74 72.07,212.99 72.51,215.49 72.29,216.74 72.29,217.18 70.59,218.88 70.29,218.88 70.24,218.93 U19.24
REFCLK3_R_DP: length 13.2
  TOP w0.127: U19.23 70.24,218.53 70.29,218.58 70.47,218.58 71.98,217.06 71.98,216.72 72.2,215.49 71.76,212.99 71.98,211.71 71.98,211.15 72.05,210.77 71.76,209.12 71.98,207.84 71.98,207.44 71.86,207.31 R201.1
SCAN_CLK: length 46.9
  TOP w0.102: P_OCP.OCP_B6 76.07,84.46 v1(76.07,84.45)
  BOTTOM w0.102: TP5.TEST 43.05,95.25 46.35,91.95 70.23,91.95 75.06,87.12 75.44,87.12 76.07,86.49 v1(76.07,84.45)
SCAN_DATA_IN: length 50.5
  TOP w0.102: P_OCP.OCP_B4 74.87,84.52 v1(74.93,84.45)
  BOTTOM w0.102: v1(74.93,84.45) 74.93,85.85 69.85,90.93 45.47,90.93 42.93,93.47 33.53,93.47 TP11.TEST
SCAN_DATA_OUT: length 47.5
  TOP w0.102: P_OCP.OCP_B5 75.47,85.19 v1(75.56,85.09)
  BOTTOM w0.102: TP14.TEST 35.43,94.11 43.31,94.11 45.97,91.44 69.98,91.44 74.8,86.61 75.06,86.61 75.56,86.11 v1(75.56,85.09)
SCAN_LD_N: length 42
  TOP w0.102: v1(74.3,85.09) 74.27,85.12 P_OCP.OCP_B3
  BOTTOM w0.102: v1(74.3,85.09) 73.66,85.72 70.1,85.72 65.41,90.42 45.09,90.42 42.8,92.71 TP3.TEST
SET2DIL_85_BOT: length 203.2
  BOTTOM w0.127: 73.02,314.23 73.26,314.23 73.33,314.3 174.44,314.3 174.44,314.6 73.36,314.6 73.28,314.68 73.02,314.68
SET2DIL_85_TOP: length 203.2
  TOP w0.127: 73.02,294.23 73.28,294.23 73.36,294.16 174.44,294.16 174.44,293.85 73.33,293.85 73.26,293.78 73.02,293.78
SI52202_1P8V: length 15.7
  TOP w0.102: L3.1 L6.1 L5.1 L4.1 63.63,248.29 63.25,247.9 62.1,247.9 61.91,247.72 U17.5
SI52202_SADR1: length 6.9
  TOP w0.102: R209.2 69.82,222.61 69.02,221.8 U19.1 U19.2 ; R209.2 R207.1 ; R209.2 70.99,223.95 70.99,225.09
SI52202_SCLK: length 13.1
  TOP w0.102: P7.2 68.1,229.31 R205.1 v1(68.07,228.47) ; U19.4 67.82,221.62 67.91,221.7 67.99,221.7 68.24,221.95 68.24,222.42 v1(68.45,222.63)
  BOTTOM w0.102: v1(68.45,222.63) 69.37,222.63 69.47,222.73 69.47,227.08 v1(68.07,228.47)
SI52202_SCLK_17037650: length 9.4
  TOP w0.102: U18.7 54.08,239.76 53.47,239.14 53.47,237.11 54.1,236.47 54.86,236.47 55.32,236.02 R191.1 55.12,235.38 P6.2
SI52202_SDA: length 13.6
  TOP w0.102: v1(66.5,229.29) R204.1 65.56,229.34 P7.3 ; v1(68.96,223.14) 68.96,222.25 68.22,221.51 U19.3
  BOTTOM w0.102: v1(68.96,223.14) 68.83,223.27 68.83,226.95 v1(66.5,229.29)
SI52202_SDA_17037650: length 8.4
  TOP w0.102: U18.6 53.68,239.74 52.5,238.56 R192.1 52.58,235.51 P6.3
SI52202_SLEWRATE_SEL: length 28.4
  TOP w0.102: P_SLEWRATE_SEL.1 58.5,215.82 R211.1 58.5,224.1 60.88,226.49 v1(70.43,226.49) ; U19.27 v1(70.41,220.13)
  BOTTOM w0.102: v1(70.41,220.13) 70.43,220.15 v1(70.43,226.49)
SI52202_VDD: length 21.3
  TOP w0.102: C135.1 C134.1 L4.2 v1(64.37,250.51) ; U18.10 55.65,240.26 v1(55.88,240.03)
  BOTTOM w0.102: v1(64.37,250.51) 64.19,250.7 59.44,250.7 55.88,247.14 v1(55.88,240.03)
SI52202_VDDA: length 12.2
  TOP w0.102: v1(54.36,244.22) 54.08,243.95 U18.19 ; C139.1 C138.1 L6.2 v1(56.75,250.51)
  BOTTOM w0.102: v1(54.36,244.22) 53.85,244.73 53.85,246.76 56.75,249.66 v1(56.75,250.51)
SI52202_VDDIO: length 13.4
  TOP w0.102: v1(56.77,244.6) 56.03,243.87 U18.15 ; C137.1 C136.1 L5.2 60.6,250.51 60.71,250.41 v1(60.71,250.06)
  BOTTOM w0.102: v1(60.71,250.06) 56.77,246.13 v1(56.77,244.6)
SI52202_VDDX: length 14.3
  TOP w0.102: v1(52.94,250.51) L3.2 C133.1 ; v1(51.94,241.17) 52.18,241.41 U18.4
  BOTTOM w0.102: v1(52.94,250.51) 52.94,247.25 51.94,246.25 v1(51.94,241.17)
SI52202_XIN: length 12.4
  TOP w0.102: U18.2 51.16,242.21 50.44,242.93 50.44,244.81 49.98,245.27 49.98,246.44 49.4,247.02 47.37,247.02 47.12,246.76 47.12,246.2 C140.2 47.19,244.23 X1.1
SI52202_XOUT: length 8.7
  TOP w0.102: U18.3 51.18,241.81 50.93,241.55 50.93,238.76 50.55,238.38 C141.2 49.49,238.41 X1.3
SLOT_ID: length 49.4
  TOP w0.102: v1(38.1,97.16) 38.1,96.9 37.34,96.14 R11.2 36.45,96.39 36.63,96.57 R9.1 ; P_OCP.OCP_B7 76.67,85.13 v1(76.71,85.09)
  BOTTOM w0.102: v1(76.71,85.09) 76.71,87.12 76.2,87.63 75.18,87.63 70.36,92.46 46.74,92.46 42.04,97.16 v1(38.1,97.16)
SMA_5IN_BOT_DN: length 127
  BOTTOM w0.127: 145.42,15.6 145.54,15.72 147.23,15.72 148.51,15.5 151.01,15.94 153.51,15.5 154.79,15.72 155.3,15.72 158.12,12.9 158.52,12.9 159.47,13.07 161.69,12.68 164.19,13.12 166.69,12.68 169.19,13.12 171.69,12.68 174.19,13.12 176.7,12.68 179.2,13.12 181.7,12.68 184.2,13.12 185.42,12.9 186.56,12.9 186.87,13.21 186.87,16.14 186.61,16.45 185.79,16.59 183.65,16.22 181.15,16.66 178.64,16.22 176.14,16.66 173.64,16.22 171.14,16.66 169.86,16.43 169.6,16.43 169.47,16.56 169.47,19.25 169.6,19.38 169.85,19.38 170.77,19.54 172.94,19.16 175.44,19.6 177.94,19.16 180.44,19.6 182.94,19.16 185.44,19.6 187.95,19.16 190.45,19.6 192.95,19.16 195.45,19.6 197.95,19.16 200.45,19.6 202.95,19.16 205.46,19.6 206.71,19.38 207.14,19.38 210.8,15.72 211.34,15.72 212.59,15.94 214.75,15.57 215.65,15.72 216.41,15.72 216.54,15.6
  BOTTOM w0.152: 145.42,15.6 P_SMA_BOT_5IN_DN_1.1 ; P_SMA_BOT_5IN_DN_2.1 216.54,15.6
SMA_5IN_BOT_DP: length 127
  BOTTOM w0.127: 216.54,16.15 216.41,16.03 215.62,16.03 214.75,15.88 212.59,16.25 211.32,16.03 210.92,16.03 207.26,19.69 206.73,19.69 205.46,19.91 202.95,19.47 200.45,19.91 197.95,19.47 195.45,19.91 192.95,19.47 190.45,19.91 187.95,19.47 185.44,19.91 182.94,19.47 180.44,19.91 177.94,19.47 175.44,19.91 172.94,19.47 170.77,19.85 169.82,19.69 169.47,19.69 169.16,19.38 169.16,16.43 169.47,16.13 169.89,16.13 171.14,16.35 173.64,15.91 176.14,16.35 178.64,15.91 181.15,16.35 183.65,15.91 185.79,16.28 186.45,16.17 186.56,16.03 186.56,13.34 186.44,13.21 185.45,13.21 184.2,13.43 181.7,12.99 179.2,13.43 176.7,12.99 174.19,13.43 171.69,12.99 169.19,13.43 166.69,12.99 164.19,13.43 161.69,12.99 159.47,13.38 158.5,13.21 158.24,13.21 155.42,16.03 154.76,16.03 153.51,15.81 151.01,16.25 148.51,15.81 147.26,16.03 145.54,16.03 145.42,16.15
  BOTTOM w0.152: P_SMA_BOT_5IN_DP_2.1 216.54,16.15 ; 145.42,16.15 P_SMA_BOT_5IN_DP_1.1
SMA_5IN_TOP_DN: length 127.1
  TOP w0.127: 198.76,157.84 198.63,157.96 197.77,157.96 196.63,157.77 194.28,158.18 191.78,157.74 190.5,157.96 190.14,157.96 187.38,160.73 186.64,160.73 185.42,160.95 182.91,160.51 180.41,160.95 177.91,160.51 175.41,160.95 172.91,160.51 170.41,160.95 167.91,160.51 165.4,160.95 162.9,160.51 160.4,160.95 157.9,160.51 155.4,160.95 152.9,160.51 151.01,160.84 150.39,160.73 149.48,160.73 149.35,160.6 149.35,156.77 149.48,156.64 149.99,156.64 151.25,156.42 153.75,156.86 156.25,156.42 158.75,156.86 160.63,156.53 161.26,156.64 162.26,156.64 163.12,155.78 163.12,153.16 161.92,151.97 161.14,151.97 160.3,152.12 158.19,151.74 155.69,152.18 153.19,151.74 150.68,152.18 148.18,151.74 145.68,152.18 143.18,151.74 140.68,152.18 138.18,151.74 136.79,151.99 136.68,151.97 135.81,151.97 129.82,157.96 129.57,157.96 128.3,157.74 125.79,158.18 124.12,157.88 123.67,157.96 122.68,157.96 122.55,157.84
  TOP w0.152: P_SMA_TOP_5IN_DN_1.1 122.55,157.84 ; 198.76,157.84 P_SMA_TOP_5IN_DN_2.1
SMA_5IN_TOP_DP: length 127.1
  TOP w0.127: 198.76,158.39 198.63,158.27 197.74,158.27 196.63,158.08 194.28,158.49 191.78,158.05 190.52,158.27 190.27,158.27 187.5,161.04 186.67,161.04 185.42,161.26 182.91,160.82 180.41,161.26 177.91,160.82 175.41,161.26 172.91,160.82 170.41,161.26 167.91,160.82 165.4,161.26 162.9,160.82 160.4,161.26 157.9,160.82 155.4,161.26 152.9,160.82 151.01,161.15 150.37,161.04 149.35,161.04 149.05,160.73 149.05,156.64 149.35,156.34 149.97,156.34 151.25,156.11 153.75,156.55 156.25,156.11 158.75,156.55 160.63,156.22 161.29,156.34 162.13,156.34 162.81,155.65 162.81,153.29 161.8,152.27 161.16,152.27 160.3,152.42 158.19,152.05 155.69,152.49 153.19,152.05 150.68,152.49 148.18,152.05 145.68,152.49 143.18,152.05 140.68,152.49 138.18,152.05 136.79,152.3 136.65,152.27 135.94,152.27 129.95,158.27 129.55,158.27 128.3,158.05 125.8,158.49 124.12,158.19 123.7,158.27 122.68,158.27 122.55,158.39
  TOP w0.152: 198.76,158.39 P_SMA_TOP_5IN_DP_2.1 ; P_SMA_TOP_5IN_DP_1.1 122.55,158.39
SMA_10IN_BOT_DN: length 254.1
  BOTTOM w0.127: 27.3,15.6 27.43,15.72 28.17,15.72 29.39,15.94 31.89,15.5 34.29,15.92 35.41,15.72 35.79,15.72 36.7,16.64 36.7,18.92 37.46,19.69 37.72,19.69 38.33,19.58 40.2,19.91 42.7,19.46 45.2,19.91 47.7,19.46 50.21,19.91 52.71,19.46 55.21,19.91 57.71,19.46 60.21,19.91 62.71,19.46 65.21,19.91 67.72,19.46 70.22,19.91 72.72,19.46 75.22,19.91 77.72,19.46 80.22,19.91 82.72,19.46 85.23,19.91 87.73,19.46 90.23,19.91 92.73,19.46 95.23,19.91 96.48,19.69 96.77,19.69 96.9,19.56 96.9,17.4 96.77,17.27 96.51,17.27 95.23,17.5 92.73,17.06 90.23,17.5 87.73,17.06 85.23,17.5 82.72,17.06 80.22,17.5 77.72,17.06 75.22,17.5 72.72,17.06 70.22,17.5 67.72,17.06 65.21,17.5 62.71,17.06 60.21,17.5 57.71,17.06 55.21,17.5 52.71,17.06 50.21,17.5 47.7,17.06 45.2,17.5 42.7,17.06 41.17,17.32 40.87,17.27 40.26,17.27 39.83,16.84 39.83,14.78 40.13,14.48 40.3,14.48 40.9,14.58 42.75,14.26 45.25,14.7 47.75,14.26 50.25,14.7 52.75,14.26 55.26,14.7 57.76,14.26 60.26,14.7 62.76,14.26 65.26,14.7 67.76,14.26 70.26,14.7 72.77,14.26 75.27,14.7 77.77,14.26 80.27,14.7 82.77,14.26 85.27,14.7 87.77,14.26 90.28,14.7 92.78,14.26 95.28,14.7 96.53,14.48 96.77,14.48 96.9,14.35 96.9,12.62 96.77,12.5 96.49,12.5 95.21,12.72 92.71,12.28 90.21,12.72 87.72,12.29 86.51,12.5 86.11,12.5 85.55,11.94 85.55,9.78 86.11,9.22 86.42,9.22 87.67,9.44 90.17,9 92.68,9.44 95.18,9 97.68,9.44 100.18,9 101.43,9.22 101.98,9.22 108.48,15.72 108.88,15.72 110.13,15.94 112.63,15.5 114.15,15.77 114.43,15.72 115.44,15.72 115.57,15.6
  BOTTOM w0.152: P_SMA_BOT_10IN_DN_2.1 115.57,15.6 ; 27.3,15.6 P_SMA_BOT_10IN_DN_1.1
SMA_10IN_BOT_DP: length 254.1
  BOTTOM w0.127: 115.57,16.15 115.44,16.03 114.45,16.03 114.15,16.08 112.63,15.81 110.13,16.25 108.85,16.03 108.36,16.03 101.85,9.53 101.4,9.53 100.18,9.31 97.68,9.75 95.18,9.31 92.68,9.75 90.17,9.31 87.67,9.75 86.4,9.53 86.23,9.53 85.85,9.91 85.85,11.81 86.23,12.19 86.49,12.19 87.72,11.98 90.21,12.41 92.71,11.97 95.21,12.41 96.47,12.19 96.9,12.19 97.21,12.5 97.21,14.48 96.9,14.78 96.56,14.78 95.28,15.01 92.78,14.57 90.28,15.01 87.77,14.57 85.27,15.01 82.77,14.57 80.27,15.01 77.77,14.57 75.27,15.01 72.77,14.57 70.26,15.01 67.76,14.57 65.26,15.01 62.76,14.57 60.26,15.01 57.76,14.57 55.26,15.01 52.75,14.57 50.25,15.01 47.75,14.57 45.25,15.01 42.75,14.57 40.9,14.89 40.27,14.78 40.26,14.78 40.13,14.91 40.13,16.71 40.39,16.97 40.89,16.97 41.17,17.02 42.7,16.75 45.2,17.19 47.7,16.75 50.21,17.19 52.71,16.75 55.21,17.19 57.71,16.75 60.21,17.19 62.71,16.75 65.21,17.19 67.72,16.75 70.22,17.19 72.72,16.75 75.22,17.19 77.72,16.75 80.22,17.19 82.72,16.75 85.23,17.19 87.73,16.75 90.23,17.19 92.73,16.75 95.23,17.19 96.48,16.97 96.9,16.97 97.21,17.27 97.21,19.68 96.9,19.99 96.51,19.99 95.23,20.22 92.73,19.77 90.23,20.22 87.73,19.77 85.23,20.22 82.72,19.77 80.22,20.22 77.72,19.77 75.22,20.22 72.72,19.77 70.22,20.22 67.72,19.77 65.21,20.22 62.71,19.77 60.21,20.22 57.71,19.77 55.21,20.22 52.71,19.77 50.21,20.22 47.7,19.77 45.2,20.22 42.7,19.77 40.2,20.22 38.33,19.89 37.75,19.99 37.34,19.99 36.4,19.05 36.4,16.76 35.66,16.03 35.43,16.03 34.29,16.23 31.89,15.81 29.39,16.25 28.14,16.03 27.43,16.03 27.3,16.15
  BOTTOM w0.152: 115.57,16.15 P_SMA_BOT_10IN_DP_2.1 ; P_SMA_BOT_10IN_DP_1.1 27.3,16.15
SMA_10IN_TOP_DN: length 254
  TOP w0.127: 122.55,180.7 122.68,180.82 123.77,180.82 125.05,180.6 127.55,181.04 129.37,180.72 129.97,180.82 130.33,180.82 132.71,183.21 134.37,183.21 135.45,183.02 137.78,183.43 140.28,182.99 142.78,183.43 145.28,182.99 147.79,183.43 150.29,182.99 152.79,183.43 155.29,182.99 157.79,183.43 160.29,182.99 162.79,183.43 165.3,182.99 167.8,183.43 170.3,182.99 172.8,183.43 175.3,182.99 177.8,183.43 179.05,183.21 180.09,183.21 180.21,183.08 180.21,180.52 180.09,180.39 179.1,180.39 177.82,180.62 175.32,180.17 172.82,180.62 170.31,180.17 167.81,180.62 165.31,180.17 162.81,180.62 160.31,180.17 157.81,180.62 155.31,180.17 152.8,180.62 150.3,180.17 147.8,180.62 145.3,180.17 142.89,180.6 141.71,180.39 141.35,180.39 141.05,180.09 141.05,177.55 141.35,177.24 141.61,177.24 141.93,177.18 143.51,177.46 146.01,177.02 148.51,177.46 151.01,177.02 153.52,177.46 156.02,177.02 158.52,177.46 161.02,177.02 163.52,177.46 166.02,177.02 168.52,177.46 171.03,177.02 173.53,177.46 176.03,177.02 177.28,177.24 177.67,177.24 177.8,177.11 177.8,174.42 177.67,174.29 177.12,174.29 175.87,174.07 173.37,174.52 170.87,174.07 168.36,174.52 165.86,174.07 163.36,174.52 160.86,174.07 158.36,174.52 155.86,174.07 153.36,174.52 150.85,174.07 148.35,174.52 145.85,174.07 144.44,174.32 144.27,174.29 144.02,174.29 143.33,173.61 143.33,171.2 144.02,170.51 144.46,170.51 145.68,170.73 148.18,170.28 150.68,170.73 153.18,170.28 155.69,170.73 158.19,170.28 160.69,170.73 163.19,170.28 165.69,170.73 168.19,170.28 170.69,170.73 173.19,170.28 175.7,170.73 178.2,170.28 180.08,170.62 180.69,170.51 181.48,170.51 191.79,180.82 192.33,180.82 193.61,180.6 196.11,181.04 197.34,180.82 198.63,180.82 198.76,180.7
  TOP w0.152: P_SMA_TOP_10IN_DN_1.1 122.55,180.7 ; 198.76,180.7 P_SMA_TOP_10IN_DN_2.1
SMA_10IN_TOP_DP: length 254
  TOP w0.127: 198.76,181.25 198.63,181.13 197.36,181.13 196.11,181.35 193.61,180.91 192.36,181.13 191.67,181.13 181.36,170.82 180.72,170.82 180.08,170.93 178.2,170.59 175.7,171.04 173.19,170.59 170.69,171.04 168.19,170.59 165.69,171.04 163.19,170.59 160.69,171.04 158.19,170.59 155.69,171.04 153.18,170.59 150.68,171.04 148.18,170.59 145.68,171.04 144.43,170.82 144.15,170.82 143.64,171.32 143.64,173.48 144.15,173.99 144.3,173.99 144.44,174.01 145.85,173.76 148.35,174.21 150.85,173.76 153.36,174.21 155.86,173.76 158.36,174.21 160.86,173.76 163.36,174.21 165.86,173.76 168.36,174.21 170.87,173.76 173.37,174.21 175.87,173.76 177.15,173.99 177.8,173.99 178.1,174.3 178.1,177.24 177.8,177.55 177.25,177.55 176.03,177.33 173.53,177.77 171.03,177.33 168.52,177.77 166.02,177.33 163.52,177.77 161.02,177.33 158.52,177.77 156.02,177.33 153.52,177.77 151.01,177.33 148.51,177.77 146.01,177.33 143.51,177.77 141.93,177.49 141.63,177.55 141.48,177.55 141.35,177.67 141.35,179.96 141.48,180.09 141.73,180.09 142.89,180.29 145.3,179.87 147.8,180.31 150.3,179.87 152.8,180.31 155.31,179.87 157.81,180.31 160.31,179.87 162.81,180.31 165.31,179.87 167.81,180.31 170.31,179.87 172.82,180.31 175.32,179.87 177.82,180.31 179.07,180.09 180.21,180.09 180.52,180.39 180.52,183.21 180.21,183.52 179.08,183.52 177.8,183.74 175.3,183.3 172.8,183.74 170.3,183.3 167.8,183.74 165.3,183.3 162.79,183.74 160.29,183.3 157.79,183.74 155.29,183.3 152.79,183.74 150.29,183.3 147.79,183.74 145.28,183.3 142.78,183.74 140.28,183.3 137.78,183.74 135.45,183.33 134.39,183.52 132.59,183.52 130.2,181.13 129.95,181.13 129.37,181.03 127.55,181.35 125.05,180.91 123.8,181.13 122.68,181.13 122.55,181.25
  TOP w0.152: P_SMA_TOP_10IN_DP_1.1 122.55,181.25 ; 198.76,181.25 P_SMA_TOP_10IN_DP_2.1
SMB_CLK: length 63.5
  TOP w0.102: P_OCP.A7 88.86,92.11 v1(88.27,92.71)
  BOTTOM w0.102: v1(88.27,92.71) 87,91.44 82.68,91.44 81.53,90.3 81.53,87.53 81.13,87.12 80.21,87.12 79.55,86.46 79.55,84.91 77.37,82.73 66.75,82.73 63.5,85.98 49.78,85.98 46.61,82.8 40.26,82.8 38.99,84.07 TP19.TEST
